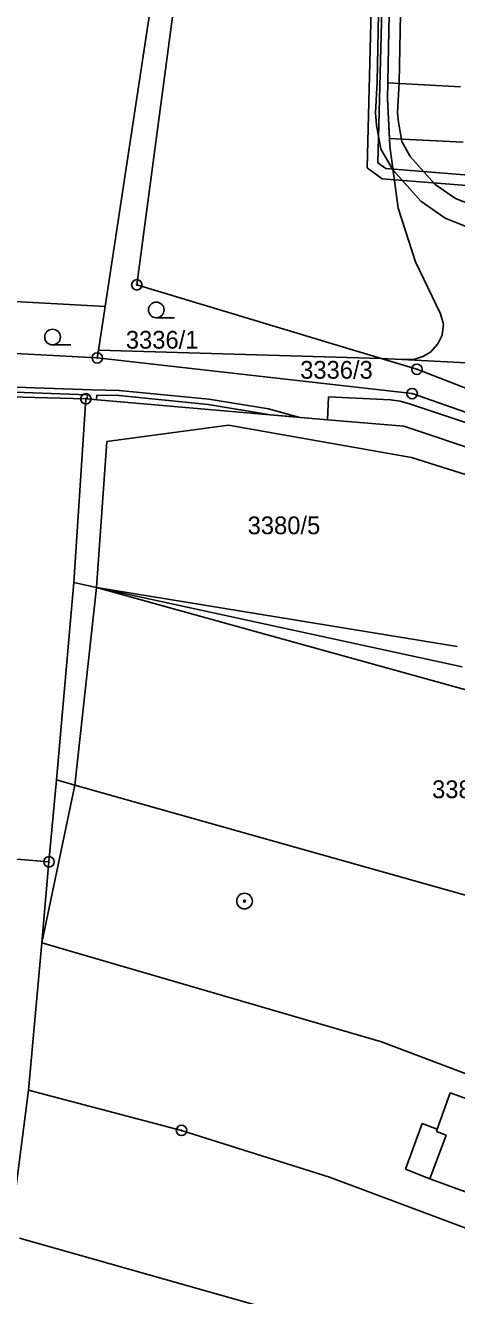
# Model space of a CAD drawing. Extents: x -593183 to -588034, y -1130415 to -1124994.
# Drawn here: x -592330.3 to -592289, y -1128513.6 to -1128391.9 of the extents above; entities that cross this region are included whole.
import ezdxf

# ---------------------------------------------------------------- set-up
doc = ezdxf.new("R2010")
doc.units = 0
for name, color, linetype in [('Vrstva 1', 7, 'Continuous'), ('Vrstva 18', 7, 'Continuous'), ('Vrstva 24', 7, 'Continuous'), ('Vrstva 25', 7, 'Continuous'), ('Vrstva 27', 7, 'Continuous'), ('Vrstva 4', 7, 'Continuous')]:
    doc.layers.add(name, color=color, linetype=linetype)

msp = doc.modelspace()

# ---------------------------------------------------------------- linework, layer by layer
at = {"layer": 'Vrstva 1'}
for p, q in [((-592315.38, -1128370.74), (-592322.67, -1128418.86)), ((-592313.52, -1128370.91), (-592319.63, -1128416.8)), ((-592295.62, -1128398.99), (-592295.2, -1128375.76)), ((-592295.62, -1128398.99), (-592295.4, -1128403.53)), ((-592295.4, -1128403.53), (-592294.62, -1128409.46)), ((-592294.62, -1128409.46), (-592292.95, -1128414.59)), ((-592292.95, -1128414.59), (-592290.56, -1128419.58)), ((-592319.63, -1128416.8), (-592296.23, -1128423.86)), ((-592343.73, -1128417.73), (-592322.67, -1128418.86)), ((-592322.67, -1128418.86), (-592323.31, -1128423.07)), ((-592290.56, -1128419.58), (-592290.27, -1128420.58)), ((-592290.27, -1128420.58), (-592290.38, -1128421.62)), ((-592290.8, -1128422.46), (-592291.52, -1128423.24)), ((-592290.38, -1128421.62), (-592290.8, -1128422.46)), ((-592344.16, -1128422.71), (-592323.42, -1128423.8)), ((-592323.31, -1128423.07), (-592323.42, -1128423.8)), ((-592323.31, -1128423.07), (-592296.23, -1128423.86)), ((-592292.23, -1128423.67), (-592293.11, -1128423.94)), ((-592291.52, -1128423.24), (-592292.23, -1128423.67)), ((-592323.42, -1128423.8), (-592293.27, -1128427.22)), ((-592296.23, -1128423.86), (-592292.81, -1128424.89)), ((-592296.23, -1128423.86), (-592294.22, -1128423.96)), ((-592293.11, -1128423.94), (-592294.22, -1128423.96)), ((-592294.22, -1128423.96), (-592277.41, -1128424.79)), ((-592292.81, -1128424.89), (-592233.79, -1128447.89)), ((-592345.74, -1128427.16), (-592324.51, -1128427.72)), ((-592293.27, -1128427.22), (-592233.79, -1128447.89)), ((-592324.51, -1128427.72), (-592325.66, -1128445.32)), ((-592324.51, -1128427.72), (-592301.38, -1128429.72)), ((-592301.27, -1128427.54), (-592301.38, -1128429.72)), ((-592301.27, -1128427.54), (-592295.34, -1128427.81)), ((-592295.34, -1128427.81), (-592294.41, -1128427.94)), ((-592294.41, -1128427.94), (-592293.44, -1128428.22)), ((-592293.44, -1128428.22), (-592275.93, -1128434.06)), ((-592301.38, -1128429.72), (-592294.06, -1128430.35)), ((-592294.06, -1128430.35), (-592281.78, -1128434.47)), ((-592325.66, -1128445.32), (-592327.33, -1128464.23)), ((-592325.66, -1128445.32), (-592323.5, -1128445.79)), ((-592323.5, -1128445.79), (-592288.48, -1128453.39)), ((-592328.04, -1128472.07), (-592327.33, -1128464.23)), ((-592327.33, -1128464.23), (-592325.56, -1128464.73)), ((-592325.56, -1128464.73), (-592281.2, -1128477.25)), ((-592349.2, -1128470.35), (-592328.04, -1128472.07)), ((-592328.04, -1128472.07), (-592328.74, -1128479.83)), ((-592328.74, -1128479.83), (-592330.01, -1128493.95)), ((-592296.19, -1128489.31), (-592328.74, -1128479.83)), ((-592255.87, -1128504.57), (-592296.19, -1128489.31)), ((-592330.01, -1128493.95), (-592331.8, -1128507.86)), ((-592330.01, -1128493.95), (-592315.35, -1128497.8)), ((-592290.87, -1128497.68), (-592289.63, -1128494.2)), ((-592289.63, -1128494.2), (-592280.21, -1128497.55)), ((-592315.35, -1128497.8), (-592301.19, -1128502.29)), ((-592293.92, -1128501.52), (-592292.31, -1128497.15)), ((-592292.31, -1128497.15), (-592290.87, -1128497.68)), ((-592291.57, -1128502.43), (-592293.92, -1128501.52)), ((-592301.19, -1128502.29), (-592263.16, -1128516.51)), ((-592283.1, -1128505.54), (-592291.57, -1128502.43)), ((-592330.86, -1128508.13), (-592306.3, -1128515.09))]:
    msp.add_line(p, q, dxfattribs=at)
at = {"layer": 'Vrstva 24'}
for centre, radius in [((-592319.63, -1128416.8), 0.5), ((-592319.63, -1128416.8), 0.0327), ((-592323.42, -1128423.8), 0.5), ((-592323.42, -1128423.8), 0.0327), ((-592292.81, -1128424.89), 0.5), ((-592292.81, -1128424.89), 0.0327), ((-592324.51, -1128427.72), 0.5), ((-592293.27, -1128427.22), 0.5), ((-592293.27, -1128427.22), 0.0327), ((-592324.51, -1128427.72), 0.0327), ((-592328.04, -1128472.07), 0.5), ((-592328.04, -1128472.07), 0.0327), ((-592309.32, -1128475.83), 0.75), ((-592309.32, -1128475.83), 0.0903), ((-592315.35, -1128497.8), 0.5), ((-592315.35, -1128497.8), 0.0327)]:
    msp.add_circle(centre, radius, dxfattribs=at)
at = {"layer": 'Vrstva 25'}
for p, q in [((-592316.02, -1128419.95), (-592317.77, -1128419.95)), ((-592325.95, -1128422.55), (-592327.7, -1128422.55))]:
    msp.add_line(p, q, dxfattribs=at)
for centre in [(-592317.77, -1128419.2), (-592327.7, -1128421.8)]:
    msp.add_circle(centre, 0.75, dxfattribs=at)
at = {"layer": 'Vrstva 27'}
for p, q in [((-592295.62, -1128398.99), (-592295.2, -1128375.76)), ((-592297.57, -1128405.6), (-592296.88, -1128378.54)), ((-592296.61, -1128397.34), (-592296.28, -1128378.1)), ((-592295.88, -1128378.56), (-592296.56, -1128405.11)), ((-592294.16, -1128378.02), (-592294.5, -1128397.42)), ((-592296.78, -1128400.33), (-592296.61, -1128397.34)), ((-592295.62, -1128398.99), (-592295.59, -1128397.46)), ((-592295.59, -1128397.46), (-592288.65, -1128397.83)), ((-592294.5, -1128397.42), (-592294.66, -1128400.31)), ((-592295.4, -1128403.53), (-592295.62, -1128398.99)), ((-592295.44, -1128402.77), (-592295.62, -1128398.99)), ((-592296.68, -1128401.51), (-592296.78, -1128400.33)), ((-592294.66, -1128400.31), (-592294.58, -1128401.23)), ((-592296.27, -1128403.8), (-592296.68, -1128401.51)), ((-592294.58, -1128401.23), (-592294.25, -1128403.08)), ((-592288.39, -1128403.14), (-592295.44, -1128402.77)), ((-592295.1, -1128405.82), (-592296.27, -1128403.8)), ((-592294.62, -1128409.46), (-592295.4, -1128403.53)), ((-592294.25, -1128403.08), (-592293.45, -1128404.5)), ((-592296.56, -1128405.11), (-592295.79, -1128405.67)), ((-592293.45, -1128404.5), (-592291.05, -1128407.19)), ((-592296.15, -1128406.65), (-592297.57, -1128405.6)), ((-592295.79, -1128405.67), (-592287.88, -1128406.28)), ((-592292.45, -1128408.79), (-592295.1, -1128405.82)), ((-592287.64, -1128407.3), (-592296.15, -1128406.65)), ((-592291.05, -1128407.19), (-592289.11, -1128408.54)), ((-592290.11, -1128410.41), (-592292.45, -1128408.79)), ((-592289.11, -1128408.54), (-592287.1, -1128409.34)), ((-592292.95, -1128414.59), (-592294.62, -1128409.46)), ((-592287.54, -1128411.44), (-592290.11, -1128410.41)), ((-592290.56, -1128419.58), (-592292.95, -1128414.59)), ((-592290.27, -1128420.58), (-592290.56, -1128419.58)), ((-592290.38, -1128421.62), (-592290.27, -1128420.58)), ((-592291.52, -1128423.24), (-592290.8, -1128422.46)), ((-592290.8, -1128422.46), (-592290.38, -1128421.62)), ((-592293.11, -1128423.94), (-592292.23, -1128423.67)), ((-592292.23, -1128423.67), (-592291.52, -1128423.24)), ((-592294.22, -1128423.96), (-592293.11, -1128423.94)), ((-592277.41, -1128424.79), (-592294.22, -1128423.96)), ((-592324.35, -1128427.33), (-592335.95, -1128426.92)), ((-592335.93, -1128426.42), (-592323.9, -1128426.85)), ((-592324.38, -1128427.73), (-592324.35, -1128427.33)), ((-592323.9, -1128426.85), (-592321.32, -1128426.91)), ((-592321.32, -1128426.91), (-592312.74, -1128427.76)), ((-592323.48, -1128427.81), (-592324.38, -1128427.73)), ((-592323.45, -1128427.36), (-592323.48, -1128427.81)), ((-592321.36, -1128427.41), (-592323.45, -1128427.36)), ((-592312.8, -1128428.26), (-592321.36, -1128427.41)), ((-592306.83, -1128429.25), (-592312.8, -1128428.26)), ((-592312.74, -1128427.76), (-592307.02, -1128428.68)), ((-592307.02, -1128428.68), (-592304.14, -1128429.48)), ((-592304.14, -1128429.48), (-592306.83, -1128429.25))]:
    msp.add_line(p, q, dxfattribs=at)
at = {"layer": 'Vrstva 4'}
for p, q in [((-592322.49, -1128431.82), (-592310.85, -1128430.23)), ((-592310.85, -1128430.23), (-592293.34, -1128433.33)), ((-592322.49, -1128431.82), (-592323.5, -1128445.79)), ((-592293.34, -1128433.33), (-592282.58, -1128436.73)), ((-592323.5, -1128445.79), (-592325.56, -1128464.73)), ((-592323.5, -1128445.79), (-592288.95, -1128451.44)), ((-592323.5, -1128445.79), (-592287.78, -1128455.69)), ((-592325.56, -1128464.73), (-592328.74, -1128479.83)), ((-592290.87, -1128497.68), (-592290.94, -1128497.9)), ((-592290.94, -1128497.9), (-592290.01, -1128498.24)), ((-592290.01, -1128498.24), (-592291.57, -1128502.43))]:
    msp.add_line(p, q, dxfattribs=at)

# ---------------------------------------------------------------- texts
at = {"layer": 'Vrstva 18'}
for s, p in [('3336/1', (-592320.68, -1128422.91)), ('3336/3', (-592303.99, -1128425.79)), ('3380/5', (-592309.02, -1128440.69)), ('3381/2', (-592291.36, -1128465.97))]:
    msp.add_text(s, height=1.7, dxfattribs=at).set_placement(p)

doc.saveas('drawing.dxf')
